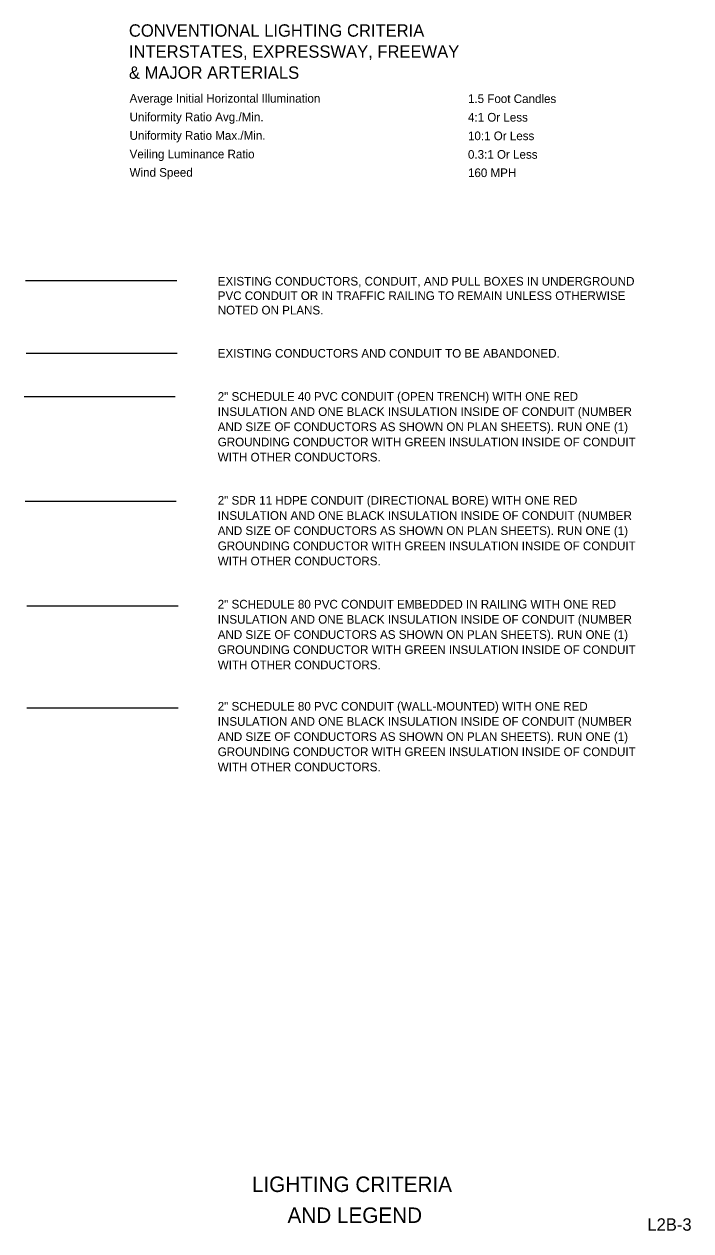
# Model space of a CAD drawing. Extents: x -0.6 to 15.1, y -0.9 to 9.2.
# Drawn here: x 9.77 to 15.15, y -0.65 to 9.1 of the extents above; entities that cross this region are included whole.
import ezdxf

# ---------------------------------------------------------------- set-up
doc = ezdxf.new("R2010")
doc.units = 0
for name, color, linetype in [('Conduit', 7, 'Continuous'), ('LiteCond_ep', 7, 'Continuous'), ('Miscellaneous1', 7, 'Continuous'), ('Miscellaneous3', 7, 'Continuous'), ('Miscellaneous7', 7, 'Continuous'), ('Miscellaneous8', 7, 'Continuous'), ('TextLabel', 7, 'Continuous'), ('TextMisc', 7, 'Continuous'), ('TextNotes', 7, 'Continuous'), ('TextShtNo', 7, 'Continuous')]:
    doc.layers.add(name, color=color, linetype=linetype)

msp = doc.modelspace()

# ---------------------------------------------------------------- linework, layer by layer
at = {"layer": 'Conduit'}
msp.add_line((9.7769, 7.0287), (10.9973, 7.0287), dxfattribs=at)
at = {"layer": 'LiteCond_ep'}
msp.add_line((9.7804, 6.4412), (11.002, 6.4412), dxfattribs=at)
at = {"layer": 'Miscellaneous1'}
msp.add_line((9.7653, 6.0925), (10.9858, 6.0925), dxfattribs=at)
at = {"layer": 'Miscellaneous3'}
msp.add_line((9.7731, 5.2468), (10.9936, 5.2468), dxfattribs=at)
at = {"layer": 'Miscellaneous7'}
msp.add_line((9.7879, 4.4019), (11.0083, 4.4019), dxfattribs=at)
at = {"layer": 'Miscellaneous8'}
msp.add_line((9.7879, 3.5774), (11.0083, 3.5774), dxfattribs=at)

# ---------------------------------------------------------------- texts
at = {"layer": 'TextLabel'}
for s, p in [('CONVENTIONAL LIGHTING CRITERIA', (10.6114, 8.9983)), ('INTERSTATES, EXPRESSWAY, FREEWAY', (10.6114, 8.8283)), ('& MAJOR ARTERIALS', (10.6114, 8.6583))]:
    msp.add_text(s, height=0.1, dxfattribs=at).set_placement(p)
at = {"layer": 'TextMisc'}
for s, p in [('EXISTING CONDUCTORS, CONDUIT, AND PULL BOXES IN UNDERGROUND ', (11.3287, 6.9883)), ('PVC CONDUIT OR IN TRAFFIC RAILING TO REMAIN UNLESS OTHERWISE ', (11.3287, 6.8716)), ('NOTED ON PLANS.', (11.3287, 6.7549)), ('EXISTING CONDUCTORS AND CONDUIT TO BE ABANDONED.', (11.3287, 6.4062)), ('2" SCHEDULE 40 PVC CONDUIT (OPEN TRENCH) WITH ONE RED ', (11.3287, 6.0575)), ('INSULATION AND ONE BLACK INSULATION INSIDE OF CONDUIT (NUMBER ', (11.3287, 5.935)), ('AND SIZE OF CONDUCTORS AS SHOWN ON PLAN SHEETS). RUN ONE (1) ', (11.3287, 5.8125)), ('GROUNDING CONDUCTOR WITH GREEN INSULATION INSIDE OF CONDUIT ', (11.3287, 5.69)), ('WITH OTHER CONDUCTORS.', (11.3287, 5.5675)), ('2" SDR 11 HDPE CONDUIT (DIRECTIONAL BORE) WITH ONE RED ', (11.3287, 5.2187)), ('INSULATION AND ONE BLACK INSULATION INSIDE OF CONDUIT (NUMBER ', (11.3287, 5.0962)), ('AND SIZE OF CONDUCTORS AS SHOWN ON PLAN SHEETS). RUN ONE (1) ', (11.3287, 4.9737)), ('GROUNDING CONDUCTOR WITH GREEN INSULATION INSIDE OF CONDUIT ', (11.3287, 4.8512)), ('WITH OTHER CONDUCTORS.', (11.3287, 4.7287)), ('2" SCHEDULE 80 PVC CONDUIT EMBEDDED IN RAILING WITH ONE RED ', (11.3287, 4.38)), ('INSULATION AND ONE BLACK INSULATION INSIDE OF CONDUIT (NUMBER ', (11.3287, 4.2575)), ('AND SIZE OF CONDUCTORS AS SHOWN ON PLAN SHEETS). RUN ONE (1) ', (11.3287, 4.135)), ('GROUNDING CONDUCTOR WITH GREEN INSULATION INSIDE OF CONDUIT ', (11.3287, 4.0125)), ('WITH OTHER CONDUCTORS.', (11.3287, 3.89)), ('2" SCHEDULE 80 PVC CONDUIT (WALL-MOUNTED) WITH ONE RED ', (11.3287, 3.5554)), ('INSULATION AND ONE BLACK INSULATION INSIDE OF CONDUIT (NUMBER ', (11.3287, 3.4329)), ('AND SIZE OF CONDUCTORS AS SHOWN ON PLAN SHEETS). RUN ONE (1) ', (11.3287, 3.3104)), ('GROUNDING CONDUCTOR WITH GREEN INSULATION INSIDE OF CONDUIT ', (11.3287, 3.1879)), ('WITH OTHER CONDUCTORS.', (11.3287, 3.0654))]:
    msp.add_text(s, height=0.07, rotation=360, dxfattribs=at).set_placement(p)
for s, p in [('   LIGHTING CRITERIA    ', (11.4651, -0.3324)), ('       AND LEGEND       ', (11.5669, -0.5824))]:
    msp.add_text(s, height=0.125, dxfattribs=at).set_placement(p)
at = {"layer": 'TextNotes'}
for s, p in [('Average Initial Horizontal Illumination', (10.6168, 8.4655)), ('1.5 Foot Candles', (13.3491, 8.4626)), ('Uniformity Ratio Avg./Min.', (10.6168, 8.3155)), ('4:1 Or Less', (13.3491, 8.3126)), ('Uniformity Ratio Max./Min.', (10.6168, 8.1655)), ('10:1 Or Less', (13.3491, 8.1626)), ('Veiling Luminance Ratio', (10.6168, 8.0155)), ('0.3:1 Or Less', (13.3491, 8.0126)), ('Wind Speed', (10.6168, 7.8673)), ('160 MPH', (13.3491, 7.8645))]:
    msp.add_text(s, height=0.07, dxfattribs=at).set_placement(p)
at = {"layer": 'TextShtNo'}
msp.add_text('L2B-3 ', height=0.1, dxfattribs=at).set_placement((14.7981, -0.6449))

doc.saveas('drawing.dxf')
